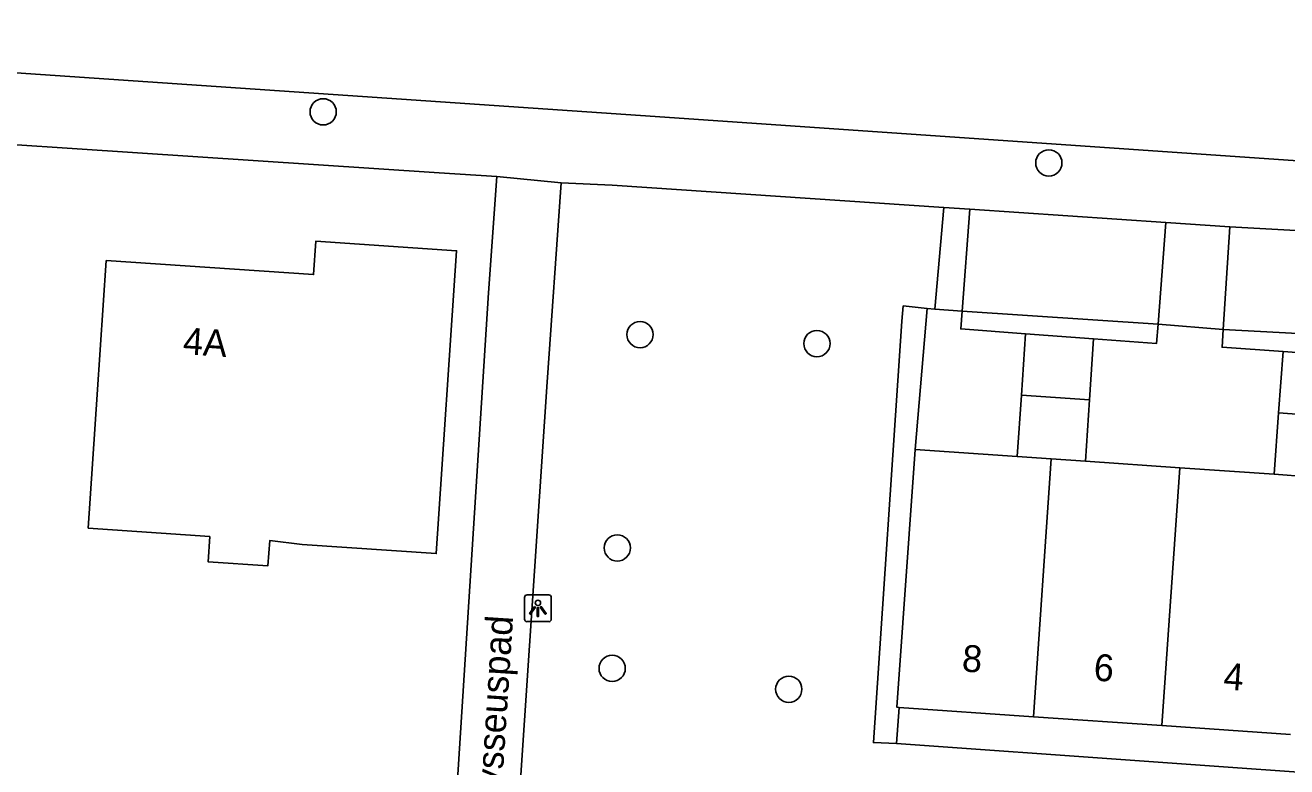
# Model space of a CAD drawing. Extents: x 161848 to 162726, y 385382 to 386521.
# Drawn here: x 162118.77 to 162165.77, y 386125.59 to 386153.2 of the extents above; entities that cross this region are included whole.
import ezdxf

# ---------------------------------------------------------------- set-up
doc = ezdxf.new("R2010")
doc.units = 0
for name, color, linetype in [('IMGEO_Boom', 7, 'Continuous'), ('IMGEO_Groenvoorziening', 7, 'Continuous'), ('IMGEO_Hek', 7, 'Continuous'), ('IMGEO_Lichtpunt', 7, 'Continuous'), ('IMGEO_Openbare_ruimte_label', 7, 'Continuous'), ('IMGEO_Pand', 7, 'Continuous'), ('IMGEO_Pand_nummerreeks', 7, 'Continuous'), ('IMGEO_Voetpad_halfverhard', 7, 'Continuous'), ('IMGEO_Voetpad_open', 7, 'Continuous')]:
    doc.layers.add(name, color=color, linetype=linetype)

msp = doc.modelspace()

# ---------------------------------------------------------------- linework, layer by layer
at = {"layer": 'IMGEO_Boom'}
for centre in [(162129.871, 386149.977), (162156.91, 386148.074), (162141.678, 386141.682), (162148.269, 386141.348), (162140.831, 386133.741), (162140.639, 386129.257), (162147.22, 386128.479)]:
    msp.add_circle(centre, 0.489, dxfattribs=at)
at = {"layer": 'IMGEO_Groenvoorziening'}
for points in [[(162151.233, 386126.464), (162150.375, 386126.495), (162151.432, 386142.179), (162151.487, 386142.75), (162152.371, 386142.654)], [(162152.371, 386142.654), (162151.929, 386137.406)], [(162152.371, 386142.654), (162152.662, 386142.632)], [(162156.044, 386141.717), (162153.628, 386141.896), (162153.678, 386142.557)], [(162160.977, 386142.07), (162153.678, 386142.557)], [(162158.578, 386141.529), (162160.922, 386141.355), (162160.977, 386142.07)], [(162163.406, 386141.875), (162163.364, 386141.214), (162165.635, 386141.052)], [(162173.092, 386141.351), (162172.906, 386141.36), (162163.406, 386141.875)]]:
    msp.add_lwpolyline(points, dxfattribs=at)
at = {"layer": 'IMGEO_Hek'}
for points in [[(162151.929, 386137.406), (162152.371, 386142.654), (162152.662, 386142.632), (162153.678, 386142.557)], [(162153.678, 386142.557), (162153.628, 386141.896), (162156.044, 386141.717)], [(162158.578, 386141.529), (162160.922, 386141.355), (162160.977, 386142.07)], [(162163.406, 386141.875), (162163.364, 386141.214), (162165.635, 386141.052)]]:
    msp.add_lwpolyline(points, dxfattribs=at)
at = {"layer": 'IMGEO_Lichtpunt'}
for p, q in [((162137.373, 386131.897), (162137.373, 386131.09)), ((162137.373, 386131.897), (162137.373, 386131.09)), ((162138.275, 386131.992), (162137.467, 386131.992)), ((162138.275, 386131.992), (162137.467, 386131.992)), ((162138.369, 386131.09), (162138.369, 386131.897)), ((162138.369, 386131.09), (162138.369, 386131.897)), ((162137.467, 386130.996), (162138.275, 386130.996)), ((162137.467, 386130.996), (162138.275, 386130.996))]:
    msp.add_line(p, q, dxfattribs=at)
for points in [[(162137.747, 386131.561), (162137.786, 386131.533), (162137.598, 386131.271), (162137.56, 386131.298), (162137.747, 386131.561)], [(162137.849, 386131.513), (162137.896, 386131.513), (162137.896, 386131.191), (162137.849, 386131.191), (162137.849, 386131.513)], [(162137.959, 386131.533), (162137.997, 386131.56), (162138.184, 386131.298), (162138.145, 386131.27), (162137.959, 386131.533)]]:
    msp.add_lwpolyline(points, dxfattribs=at)
msp.add_circle((162137.872, 386131.695), 0.0994, dxfattribs=at)
for centre, start, end in [((162137.467, 386131.897), 90, 180), ((162137.467, 386131.897), 90, 180), ((162138.275, 386131.897), 0, 90), ((162138.275, 386131.897), 0, 90), ((162137.467, 386131.09), 180, 270), ((162137.467, 386131.09), 180, 270), ((162138.275, 386131.09), 270, 0), ((162138.275, 386131.09), 270, 360)]:
    msp.add_arc(centre, 0.0946, start, end, dxfattribs=at)
at = {"layer": 'IMGEO_Pand'}
for points in [[(162121.112, 386134.473), (162121.451, 386139.453), (162121.791, 386144.438), (162129.513, 386143.915), (162129.597, 386145.161), (162134.842, 386144.806), (162134.082, 386133.529), (162129.094, 386133.869), (162127.878, 386134.012), (162127.814, 386133.075), (162125.582, 386133.227), (162125.646, 386134.164), (162121.112, 386134.473)], [(162155.888, 386139.432), (162156.044, 386141.717)], [(162156.044, 386141.717), (162158.578, 386141.529)], [(162158.578, 386141.529), (162158.424, 386139.251)], [(162165.635, 386141.052), (162165.471, 386138.767)], [(162168.169, 386140.871), (162165.635, 386141.052)], [(162155.732, 386137.147), (162155.888, 386139.432)], [(162158.424, 386139.251), (162155.888, 386139.432)], [(162158.424, 386139.251), (162158.27, 386136.97)], [(162165.471, 386138.767), (162165.306, 386136.481)], [(162165.471, 386138.767), (162168.012, 386138.585)], [(162151.334, 386127.802), (162151.246, 386127.808), (162151.929, 386137.406)], [(162151.929, 386137.406), (162155.732, 386137.147)], [(162157.001, 386137.059), (162155.732, 386137.147)], [(162156.334, 386127.458), (162157.001, 386137.059)], [(162158.27, 386136.97), (162157.001, 386137.059)], [(162158.27, 386136.97), (162161.788, 386136.726)], [(162161.788, 386136.726), (162161.121, 386127.128)], [(162161.788, 386136.726), (162165.306, 386136.481)], [(162165.306, 386136.481), (162166.581, 386136.392)], [(162156.334, 386127.458), (162151.334, 386127.802)], [(162161.121, 386127.128), (162156.334, 386127.458)], [(162165.914, 386126.798), (162161.121, 386127.128)]]:
    msp.add_lwpolyline(points, dxfattribs=at)
at = {"layer": 'IMGEO_Voetpad_halfverhard'}
for points in [[(162152.662, 386142.632), (162152.991, 386146.413)], [(162153.964, 386146.347), (162153.678, 386142.557)], [(162160.977, 386142.07), (162161.266, 386145.851)], [(162163.647, 386145.689), (162163.406, 386141.875)], [(162153.678, 386142.557), (162152.662, 386142.632)], [(162163.406, 386141.875), (162160.977, 386142.07)]]:
    msp.add_lwpolyline(points, dxfattribs=at)
at = {"layer": 'IMGEO_Voetpad_open'}
for points in [[(162118.128, 386155.403), (162117.889, 386151.469), (162141.7, 386149.843), (162171.421, 386147.793)], [(162104.58, 386149.664), (162134.192, 386147.708), (162136.336, 386147.572)], [(162132.861, 386094.776), (162133.364, 386102.051), (162133.993, 386111.254), (162136.037, 386143.241), (162136.336, 386147.572)], [(162136.336, 386147.572), (162138.742, 386147.328)], [(162138.742, 386147.328), (162138.211, 386139.742), (162136.908, 386120.46)], [(162138.742, 386147.328), (162140.635, 386147.252), (162152.991, 386146.413)], [(162152.991, 386146.413), (162153.964, 386146.347)], [(162153.964, 386146.347), (162161.266, 386145.851)], [(162161.266, 386145.851), (162163.647, 386145.689)], [(162163.647, 386145.689), (162171.459, 386145.261)], [(162151.334, 386127.802), (162151.233, 386126.464)], [(162151.233, 386126.464), (162169.342, 386125.174), (162169.081, 386121.511)]]:
    msp.add_lwpolyline(points, dxfattribs=at)

# ---------------------------------------------------------------- texts
at = {"layer": 'IMGEO_Openbare_ruimte_label'}
msp.add_text('Odysseuspad', height=1, rotation=86.2736, dxfattribs=at).set_placement((162136.418, 386123.033))
at = {"layer": 'IMGEO_Pand_nummerreeks'}
for s, rotation, p in [('4A', 356.1254, (162124.628, 386140.958)), ('8', 355.869, (162153.65, 386129.147)), ('6', 355.8575, (162158.557, 386128.809)), ('4', 355.8632, (162163.392, 386128.476))]:
    msp.add_text(s, height=1, rotation=rotation, dxfattribs=at).set_placement(p)

doc.saveas('drawing.dxf')
